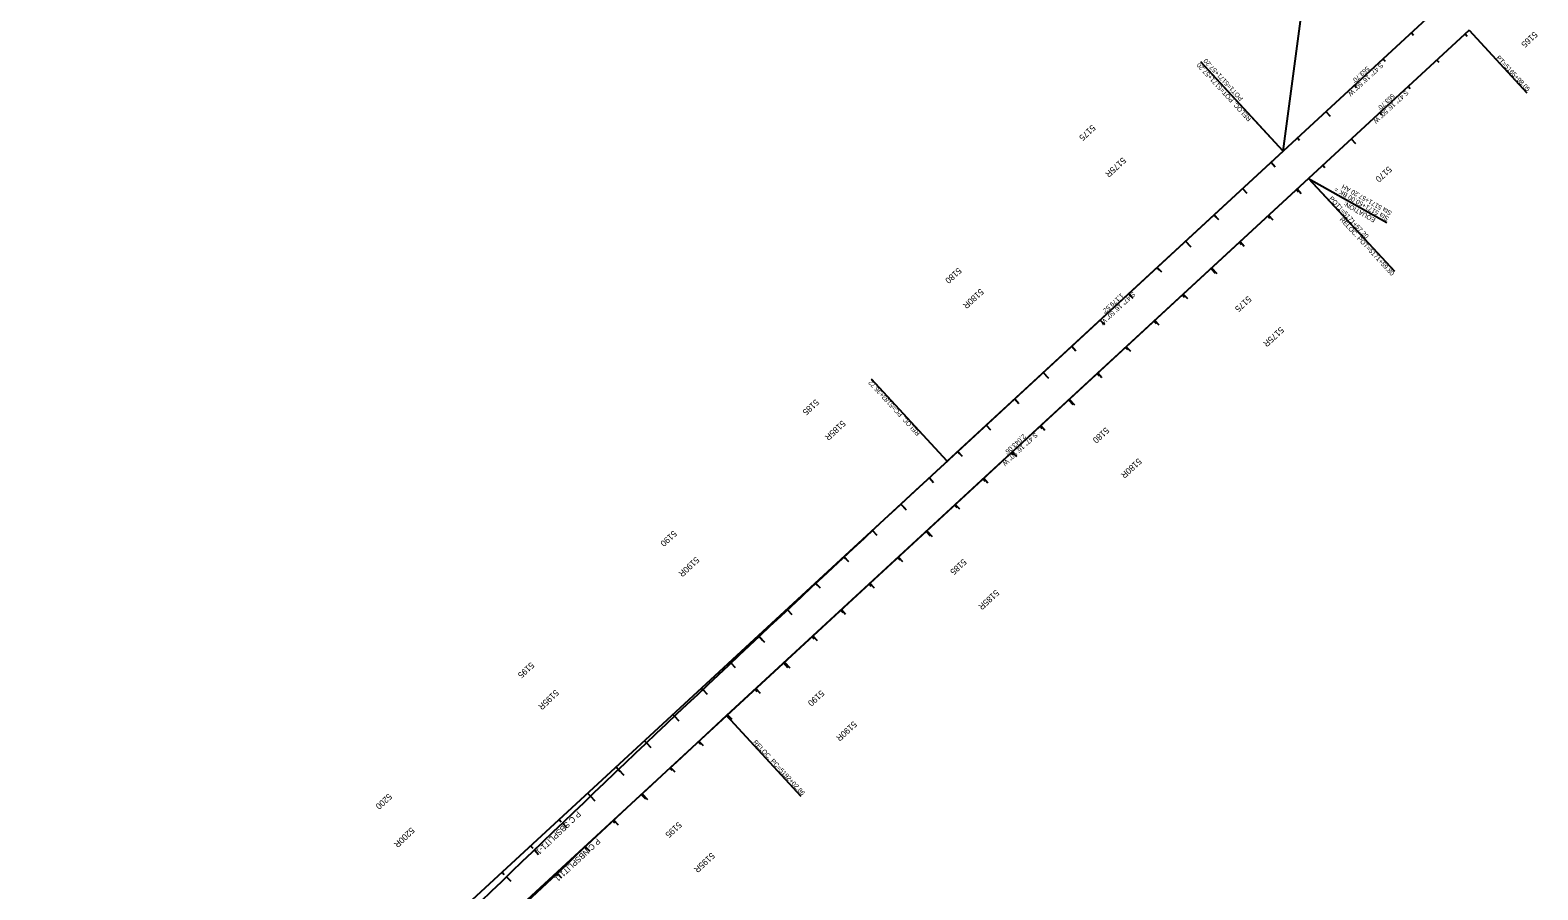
# Model space of a CAD drawing. Extents: x 2160877 to 2175861, y 601747 to 617724.
# Drawn here: x 2168975 to 2172864, y 611869 to 614087 of the extents above; entities that cross this region are included whole.
import ezdxf

# ---------------------------------------------------------------- set-up
doc = ezdxf.new("R2010")
doc.units = 0
for name, color, linetype in [('RD_HC_Cl', 7, 'Continuous'), ('RD_HC_CL_Rel', 7, 'Continuous'), ('RD_HC_Data', 7, 'Continuous'), ('RD_HC_Data_Rel', 7, 'Continuous'), ('RD_HC_Data_Tic', 7, 'Continuous'), ('RD_HC_Data_Tic_Rel', 7, 'Continuous'), ('RD_HC_TX_Rel_Sta50', 7, 'Continuous'), ('RD_HC_TX_Rel_StaOther', 7, 'Continuous'), ('RD_HC_TX_StaOther', 7, 'Continuous')]:
    doc.layers.add(name, color=color, linetype=linetype)

msp = doc.modelspace()

# ---------------------------------------------------------------- linework, layer by layer
at = {"layer": 'RD_HC_Cl'}
for p, q in [((2172621.5, 614157.6), (2172207.3, 613775.1)), ((2172686.6, 614087), (2172272.5, 613704.6)), ((2172207.3, 613775.1), (2163672.2, 605893.8)), ((2172272.5, 613704.6), (2163737.4, 605823.3))]:
    msp.add_line(p, q, dxfattribs=at)
at = {"layer": 'RD_HC_CL_Rel'}
for p, q in [((2172207.3, 613775.1), (2171340.7, 612974.9)), ((2172272.5, 613704.6), (2170771.4, 612318.6))]:
    msp.add_line(p, q, dxfattribs=at)
for centre, radius in [((2222221.5, 557873.6), 75000), ((2219616.9, 559421.3), 72000)]:
    msp.add_arc(centre, radius, 132.719474, 134.517591, dxfattribs=at)
at = {"layer": 'RD_HC_Data'}
for p, q in [((2172207.3, 613775.1), (2172285.1, 614364.1)), ((2172686.6, 614087), (2172836, 613925.2)), ((2172207.3, 613775.1), (2171994.9, 614005.2)), ((2172272.5, 613704.6), (2172474.3, 613590.3)), ((2172272.5, 613704.6), (2172421.7, 613543))]:
    msp.add_line(p, q, dxfattribs=at)
at = {"layer": 'RD_HC_Data_Rel'}
for p, q in [((2172207.3, 613775.1), (2171998.5, 614001.3)), ((2172272.5, 613704.6), (2172493.8, 613464.9)), ((2171340.7, 612974.9), (2171145.2, 613186.7)), ((2170771.4, 612318.6), (2170963.2, 612110.9))]:
    msp.add_line(p, q, dxfattribs=at)
at = {"layer": 'RD_HC_Data_Tic'}
for p, q in [((2172537.9, 614080.4), (2172543.4, 614074.5)), ((2172676.5, 614077.7), (2172682, 614071.9)), ((2172464.5, 614012.6), (2172469.9, 614006.7)), ((2172603.1, 614009.9), (2172608.5, 614004)), ((2172391, 613944.7), (2172396.4, 613938.9)), ((2172529.6, 613942.1), (2172535, 613936.2)), ((2172317.5, 613876.9), (2172328.4, 613865.1)), ((2172456.1, 613874.2), (2172461.5, 613868.3)), ((2172244.1, 613809.1), (2172249.5, 613803.2)), ((2172382.7, 613806.4), (2172393.5, 613794.6)), ((2172175.9, 613746.1), (2172181.3, 613740.2)), ((2172309.2, 613738.5), (2172314.6, 613732.7)), ((2172102.4, 613678.3), (2172107.8, 613672.4)), ((2172241, 613675.6), (2172246.4, 613669.7)), ((2172028.9, 613610.4), (2172034.4, 613604.5)), ((2172167.5, 613607.7), (2172173, 613601.9)), ((2171955.5, 613542.6), (2171966.3, 613530.8)), ((2172094.1, 613539.9), (2172099.5, 613534)), ((2171882, 613474.7), (2171887.4, 613468.9)), ((2172020.6, 613472.1), (2172031.5, 613460.3)), ((2171808.5, 613406.9), (2171814, 613401)), ((2171947.1, 613404.2), (2171952.6, 613398.3)), ((2171735.1, 613339.1), (2171740.5, 613333.2)), ((2171873.7, 613336.4), (2171879.1, 613330.5)), ((2171661.6, 613271.2), (2171667, 613265.3)), ((2171800.2, 613268.5), (2171805.6, 613262.7)), ((2171588.1, 613203.4), (2171599, 613191.6)), ((2171726.7, 613200.7), (2171732.2, 613194.8)), ((2171514.7, 613135.5), (2171520.1, 613129.7)), ((2171653.3, 613132.8), (2171664.1, 613121.1)), ((2171441.2, 613067.7), (2171446.6, 613061.8)), ((2171579.8, 613065), (2171585.2, 613059.1)), ((2171367.7, 612999.9), (2171373.2, 612994)), ((2171506.3, 612997.2), (2171511.8, 612991.3)), ((2171294.3, 612932), (2171299.7, 612926.1)), ((2171432.9, 612929.3), (2171438.3, 612923.4)), ((2171220.8, 612864.2), (2171231.6, 612852.4)), ((2171359.4, 612861.5), (2171364.8, 612855.6)), ((2171147.3, 612796.3), (2171152.7, 612790.5)), ((2171285.9, 612793.6), (2171296.8, 612781.9)), ((2171073.9, 612728.5), (2171079.3, 612722.6)), ((2171212.4, 612725.8), (2171217.9, 612719.9)), ((2171000.4, 612660.7), (2171005.8, 612654.8)), ((2171139, 612658), (2171144.4, 612652.1)), ((2170926.9, 612592.8), (2170932.3, 612586.9)), ((2171065.5, 612590.1), (2171070.9, 612584.2)), ((2170853.4, 612525), (2170864.3, 612513.2)), ((2170992, 612522.3), (2170997.5, 612516.4)), ((2170780, 612457.1), (2170785.4, 612451.3)), ((2170918.6, 612454.4), (2170929.4, 612442.7)), ((2170706.5, 612389.3), (2170711.9, 612383.4)), ((2170845.1, 612386.6), (2170850.5, 612380.7)), ((2170633, 612321.4), (2170638.5, 612315.6)), ((2170771.6, 612318.8), (2170777.1, 612312.9)), ((2170559.6, 612253.6), (2170565, 612247.7)), ((2170698.2, 612250.9), (2170703.6, 612245)), ((2170486.1, 612185.8), (2170497, 612174)), ((2170624.7, 612183.1), (2170630.1, 612177.2)), ((2170412.6, 612117.9), (2170418.1, 612112)), ((2170551.2, 612115.2), (2170562.1, 612103.5)), ((2170339.2, 612050.1), (2170344.6, 612044.2)), ((2170477.8, 612047.4), (2170483.2, 612041.5)), ((2170265.7, 611982.2), (2170271.1, 611976.4)), ((2170404.3, 611979.6), (2170409.7, 611973.7)), ((2170192.2, 611914.4), (2170197.7, 611908.5)), ((2170330.8, 611911.7), (2170336.3, 611905.8))]:
    msp.add_line(p, q, dxfattribs=at)
at = {"layer": 'RD_HC_Data_Tic_Rel'}
for p, q in [((2172175.9, 613746.1), (2172186.7, 613734.4)), ((2172102.4, 613678.3), (2172113.3, 613666.5)), ((2172242.9, 613677.3), (2172253.8, 613665.6)), ((2172028.9, 613610.4), (2172039.8, 613598.7)), ((2172169.4, 613609.5), (2172180.3, 613597.7)), ((2171955.5, 613542.6), (2171969, 613527.9)), ((2172096, 613541.7), (2172106.8, 613529.9)), ((2171882, 613474.7), (2171892.9, 613463)), ((2172022.5, 613473.8), (2172036.1, 613459.1)), ((2171808.5, 613406.9), (2171819.4, 613395.1)), ((2171949, 613406), (2171959.9, 613394.2)), ((2171735.1, 613339.1), (2171745.9, 613327.3)), ((2171875.6, 613338.1), (2171886.4, 613326.4)), ((2171661.6, 613271.2), (2171672.5, 613259.5)), ((2171802.1, 613270.3), (2171813, 613258.5)), ((2171588.1, 613203.4), (2171601.7, 613188.7)), ((2171728.6, 613202.5), (2171739.5, 613190.7)), ((2171514.7, 613135.5), (2171525.5, 613123.8)), ((2171655.2, 613134.6), (2171668.7, 613119.9)), ((2171441.2, 613067.7), (2171452.1, 613055.9)), ((2171581.7, 613066.8), (2171592.6, 613055)), ((2171367.7, 612999.9), (2171378.6, 612988.1)), ((2171508.2, 612998.9), (2171519.1, 612987.2)), ((2171294.3, 612932), (2171305.1, 612920.2)), ((2171434.8, 612931.1), (2171445.6, 612919.3)), ((2171220.9, 612864), (2171234.5, 612849.4)), ((2171361.3, 612863.2), (2171372.2, 612851.5)), ((2171147.6, 612796), (2171158.5, 612784.3)), ((2171287.8, 612795.4), (2171301.4, 612780.7)), ((2171074.5, 612727.8), (2171085.4, 612716.1)), ((2171214.4, 612727.6), (2171225.2, 612715.8)), ((2171001.4, 612659.6), (2171012.3, 612647.9)), ((2171140.9, 612659.7), (2171151.7, 612648)), ((2171067.4, 612591.9), (2171078.3, 612580.1)), ((2170928.4, 612591.3), (2170939.3, 612579.6)), ((2170855.4, 612522.8), (2170869.1, 612508.2)), ((2170994, 612524), (2171004.8, 612512.3)), ((2170782.6, 612454.3), (2170793.6, 612442.6)), ((2170920.5, 612456.2), (2170934.1, 612441.5)), ((2170709.9, 612385.6), (2170720.9, 612374)), ((2170847, 612388.4), (2170857.9, 612376.6)), ((2170773.5, 612320.5), (2170784.4, 612308.8)), ((2170637.3, 612316.9), (2170648.3, 612305.3)), ((2170564.7, 612248.1), (2170575.7, 612236.5)), ((2170700.1, 612252.6), (2170711, 612240.9)), ((2170492.3, 612179.2), (2170506.1, 612164.7)), ((2170626.8, 612184.6), (2170637.7, 612172.9)), ((2170419.9, 612110.1), (2170431, 612098.6)), ((2170553.6, 612116.5), (2170567.2, 612101.9)), ((2170480.4, 612048.4), (2170491.3, 612036.7)), ((2170347.6, 612041), (2170358.7, 612029.5)), ((2170275.5, 611971.8), (2170286.5, 611960.3)), ((2170407.4, 611980.1), (2170418.3, 611968.4)), ((2170203.4, 611902.5), (2170214.5, 611891)), ((2170334.4, 611911.7), (2170345.4, 611900))]:
    msp.add_line(p, q, dxfattribs=at)

# ---------------------------------------------------------------- texts
at = {"layer": 'RD_HC_Data'}
for s, rotation, p in [('POT1=5171+57.20', 132.7195, (2172104.7, 613911.1)), ('PT=5165+98.05', 312.7195, (2172755.9, 614014.9)), ('Sta 5171+57.20 AH', 150.4677, (2172488.7, 613618.3)), ('POT1=5171+57.20', 312.7195, (2172324.6, 613651.5)), ('Sta 5171+50.00 BK = ', 150.4677, (2172480.8, 613604.4)), ('EQUATION:', 150.4677, (2172446.6, 613600.5))]:
    msp.add_text(s, height=12, rotation=rotation, dxfattribs=at).set_placement(p)
at = {"layer": 'RD_HC_Data_Rel'}
for s, height, rotation, p in [('RELOC. POT=5171+57.20', 12, 132.7195, (2172125.6, 613858.5)), ('RELOC. POT=5171+59.80', 12, 312.7195, (2172351.8, 613597.6)), ('RELOC. PC=5183+36.72', 12, 132.7195, (2171271.4, 613047.1)), ('RELOC. PC=5192+02.86', 12, 312.7195, (2170838.9, 612248.9)), ('P C SBSPLIT1-1', 15, 223.5528, (2170386.8, 612072.9)), ('P C NBSPLIT1-1', 15, 222.7536, (2170437.4, 612002.5))]:
    msp.add_text(s, height=height, rotation=rotation, dxfattribs=at).set_placement(p)
at = {"layer": 'RD_HC_TX_Rel_Sta50'}
for s, rotation, p in [('5175R', 222.7195, (2171792.7, 613760.1)), ('5180R', 222.7195, (2171425.6, 613421.1)), ('5175R', 222.7195, (2172200.2, 613322.6)), ('5185R', 222.8442, (2171069.3, 613081.3)), ('5180R', 222.7195, (2171833.1, 612983.6)), ('5190R', 223.2262, (2170691.9, 612729.3)), ('5185R', 222.7195, (2171465.5, 612644.2)), ('5195R', 223.6082, (2170329.4, 612386.5)), ('5190R', 222.7195, (2171098.4, 612305.2)), ('5200R', 223.9901, (2169957.2, 612031.3)), ('5195R', 222.9559, (2170731.8, 611966.1))]:
    msp.add_text(s, height=16, rotation=rotation, dxfattribs=at).set_placement(p)
at = {"layer": 'RD_HC_TX_Rel_StaOther'}
for s, p in [('S 47%%d 16\' 50" W', (2171819.1, 613412.6)), ("1,179.52'", (2171788.7, 613409)), ('S 47%%d 16\' 50" W', (2171567, 613049.2)), ("2,043.06'", (2171536.6, 613045.6))]:
    msp.add_text(s, height=12, rotation=222.7195, dxfattribs=at).set_placement(p)
at = {"layer": 'RD_HC_TX_StaOther'}
for s, height, rotation, p in [('5165', 16, 223.1104, (2172854.4, 614084.7)), ('S 47%%d 16\' 50" W', 12, 222.7195, (2172458.6, 614003.1)), ("563.70'", 12, 222.7195, (2172423, 613994.7)), ('S 47%%d 16\' 50" W', 12, 222.7195, (2172523.8, 613932.6)), ("563.70'", 12, 222.7195, (2172488.2, 613924.2)), ('5175', 16, 222.7195, (2171714, 613844.1)), ('5170', 16, 222.7195, (2172478.5, 613737)), ('5180', 16, 222.7195, (2171368.6, 613475.5)), ('5175', 16, 222.7195, (2172116.1, 613402.3)), ('5185', 16, 222.7195, (2171000.9, 613136)), ('5180', 16, 222.7195, (2171749.1, 613063.5)), ('5190', 16, 222.7195, (2170633.9, 612797.1)), ('5185', 16, 222.7195, (2171381.4, 612723.9)), ('5195', 16, 222.7195, (2170266.2, 612457.5)), ('5190', 16, 222.7195, (2171014.4, 612385)), ('5200', 16, 222.7195, (2169899.3, 612118.7)), ('5195', 16, 222.7195, (2170646.7, 612045.5))]:
    msp.add_text(s, height=height, rotation=rotation, dxfattribs=at).set_placement(p)

doc.saveas('drawing.dxf')
